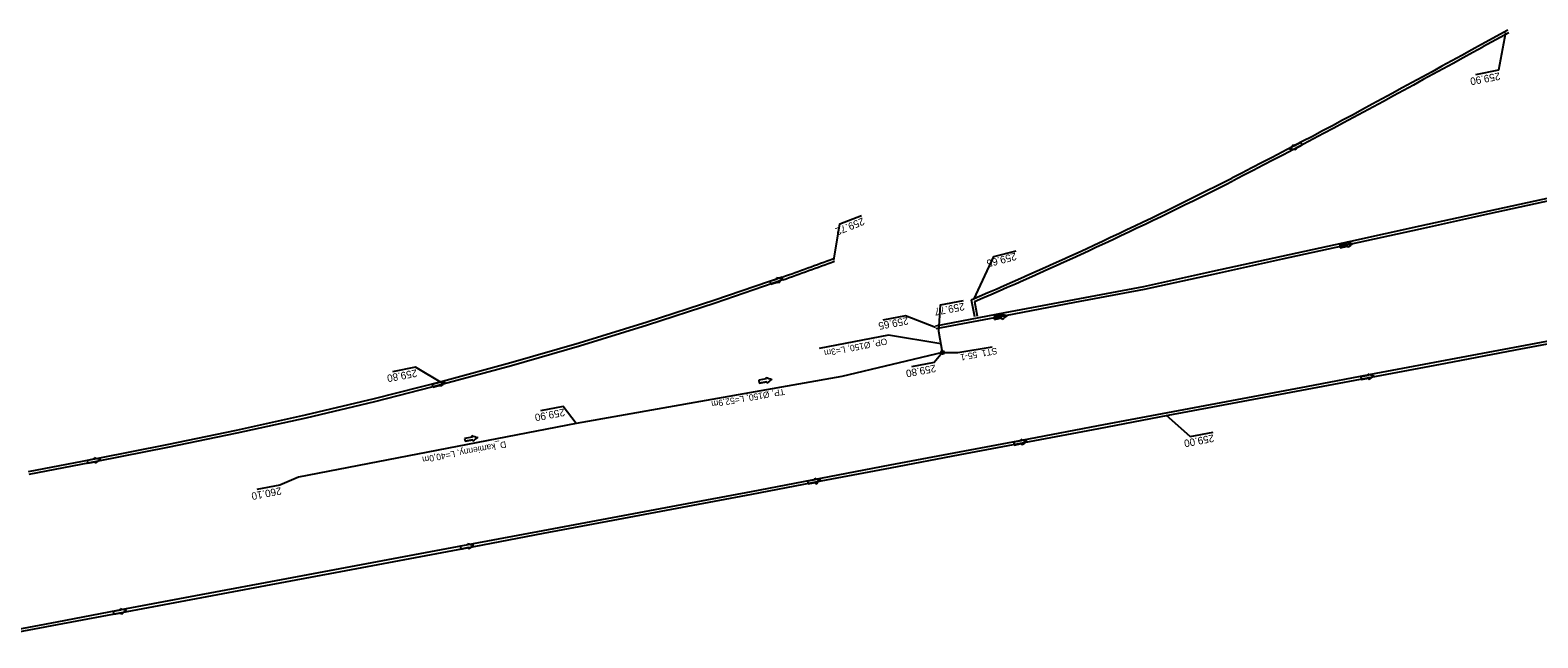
# Model space of a CAD drawing. Extents: x -1 to 65640748, y -22 to 5530284.
# Drawn here: x 6563824 to 6564037.5, y 5529873.9 to 5529959.9 of the extents above; entities that cross this region are included whole.
import ezdxf

# ---------------------------------------------------------------- set-up
doc = ezdxf.new("R2010")
doc.units = 0
for name, color, linetype in [('TOR_PS_ODW-drenaze', 7, 'Continuous'), ('TOR_PS_ODW-kolektory', 7, 'Continuous'), ('TOR_PS_ODW-studnie PEHD', 7, 'Continuous'), ('TOR_PS_OPIS_O-opisy rurociagow', 7, 'Continuous'), ('TOR_PS_OPIS_O-opisy studni', 7, 'Continuous'), ('TOR_PS_OPIS_T-INFO', 7, 'Continuous'), ('TOR_PS_T-rowy otwarte umocnione', 7, 'Continuous')]:
    doc.layers.add(name, color=color, linetype=linetype)

msp = doc.modelspace()

# ---------------------------------------------------------------- linework, layer by layer
at = {"layer": 'TOR_PS_ODW-drenaze'}
msp.add_line((6563901.29, 5529904.25), (6563862.01, 5529896.65), dxfattribs=at)
msp.add_lwpolyline([(6563953.18, 5529914.29), (6563938.93, 5529910.89), (6563901.29, 5529904.25)], dxfattribs=at)
at = {"layer": 'TOR_PS_ODW-kolektory'}
msp.add_line((6563953.18, 5529914.29), (6563952.63, 5529917.24), dxfattribs=at)
at = {"layer": 'TOR_PS_ODW-studnie PEHD'}
for radius in [0.25, 0.25, 0.25, 0.125, 0.125, 0.112]:
    msp.add_circle((6563953.18, 5529914.29), radius, dxfattribs=at)
at = {"layer": 'TOR_PS_OPIS_O-opisy rurociagow'}
for p, q in [((6564003.91, 5529944.02), (6564002.94, 5529943.51)), ((6564002.94, 5529943.51), (6564003.91, 5529944.02)), ((6564004.1, 5529943.67), (6564003.91, 5529944.02)), ((6564004.1, 5529943.67), (6564003.91, 5529944.02)), ((6564003.13, 5529943.16), (6564004.1, 5529943.67)), ((6564003.13, 5529943.16), (6564004.1, 5529943.67)), ((6564010.46, 5529929.73), (6564009.4, 5529929.5)), ((6564010.46, 5529929.73), (6564009.4, 5529929.5)), ((6564009.4, 5529929.5), (6564009.48, 5529929.11)), ((6564009.4, 5529929.5), (6564009.48, 5529929.11)), ((6564009.48, 5529929.11), (6564010.55, 5529929.34)), ((6564010.55, 5529929.34), (6564009.48, 5529929.11)), ((6563929.76, 5529924.68), (6563928.73, 5529924.33)), ((6563929.76, 5529924.68), (6563928.73, 5529924.33)), ((6563928.73, 5529924.33), (6563928.86, 5529923.95)), ((6563928.73, 5529924.33), (6563928.86, 5529923.95)), ((6563928.86, 5529923.95), (6563929.89, 5529924.3)), ((6563929.89, 5529924.3), (6563928.86, 5529923.95)), ((6563961.51, 5529919.57), (6563960.44, 5529919.37)), ((6563961.51, 5529919.57), (6563960.44, 5529919.37)), ((6563960.44, 5529919.37), (6563960.51, 5529918.98)), ((6563960.44, 5529919.37), (6563960.51, 5529918.98)), ((6563960.51, 5529918.98), (6563961.59, 5529919.18)), ((6563961.59, 5529919.18), (6563960.51, 5529918.98)), ((6563881.96, 5529910.07), (6563880.91, 5529909.78)), ((6563881.96, 5529910.07), (6563880.91, 5529909.78)), ((6563880.91, 5529909.78), (6563881.01, 5529909.39)), ((6563880.91, 5529909.78), (6563881.01, 5529909.39)), ((6563928.22, 5529910.55), (6563927.15, 5529910.36)), ((6563928.22, 5529910.55), (6563927.15, 5529910.36)), ((6563927.15, 5529910.36), (6563927.22, 5529909.97)), ((6563927.15, 5529910.36), (6563927.22, 5529909.97)), ((6563927.22, 5529909.97), (6563928.29, 5529910.16)), ((6563928.29, 5529910.16), (6563927.22, 5529909.97)), ((6564013.46, 5529911.06), (6564012.38, 5529910.86)), ((6564013.46, 5529911.06), (6564012.38, 5529910.86)), ((6564012.38, 5529910.86), (6564012.46, 5529910.46)), ((6564012.38, 5529910.86), (6564012.46, 5529910.46)), ((6564012.46, 5529910.46), (6564013.53, 5529910.67)), ((6564013.53, 5529910.67), (6564012.46, 5529910.46)), ((6563881.01, 5529909.39), (6563882.06, 5529909.68)), ((6563882.06, 5529909.68), (6563881.01, 5529909.39)), ((6563886.59, 5529902.34), (6563885.51, 5529902.15)), ((6563886.59, 5529902.34), (6563885.51, 5529902.15)), ((6563885.51, 5529902.15), (6563885.58, 5529901.76)), ((6563885.51, 5529902.15), (6563885.58, 5529901.76)), ((6563885.58, 5529901.76), (6563886.66, 5529901.95)), ((6563886.66, 5529901.95), (6563885.58, 5529901.76)), ((6563964.32, 5529901.8), (6563963.25, 5529901.6)), ((6563964.32, 5529901.8), (6563963.25, 5529901.6)), ((6563963.25, 5529901.6), (6563963.32, 5529901.2)), ((6563963.25, 5529901.6), (6563963.32, 5529901.2)), ((6563963.32, 5529901.2), (6563964.39, 5529901.41)), ((6563964.39, 5529901.41), (6563963.32, 5529901.2)), ((6563833.16, 5529899.23), (6563832.09, 5529899.02)), ((6563833.16, 5529899.23), (6563832.09, 5529899.02)), ((6563832.09, 5529899.02), (6563832.16, 5529898.63)), ((6563832.09, 5529899.02), (6563832.16, 5529898.63)), ((6563832.16, 5529898.63), (6563833.23, 5529898.84)), ((6563833.23, 5529898.84), (6563832.16, 5529898.63)), ((6563935.14, 5529896.29), (6563934.06, 5529896.09)), ((6563935.14, 5529896.29), (6563934.06, 5529896.09)), ((6563934.06, 5529896.09), (6563934.14, 5529895.7)), ((6563934.06, 5529896.09), (6563934.14, 5529895.7)), ((6563934.14, 5529895.7), (6563935.21, 5529895.9)), ((6563935.21, 5529895.9), (6563934.14, 5529895.7)), ((6563885.99, 5529887.08), (6563884.92, 5529886.88)), ((6563885.99, 5529887.08), (6563884.92, 5529886.88)), ((6563884.92, 5529886.88), (6563884.99, 5529886.49)), ((6563884.92, 5529886.88), (6563884.99, 5529886.49)), ((6563884.99, 5529886.49), (6563886.06, 5529886.69)), ((6563886.06, 5529886.69), (6563884.99, 5529886.49)), ((6563836.85, 5529877.87), (6563835.77, 5529877.67)), ((6563836.85, 5529877.87), (6563835.77, 5529877.67)), ((6563835.77, 5529877.67), (6563835.85, 5529877.28)), ((6563835.77, 5529877.67), (6563835.85, 5529877.28)), ((6563835.85, 5529877.28), (6563836.92, 5529877.48)), ((6563836.92, 5529877.48), (6563835.85, 5529877.28))]:
    msp.add_line(p, q, dxfattribs=at)
for points in [[(6564002.85, 5529943.72), (6564002.85, 5529943.72)], [(6564003.25, 5529942.96), (6564003.25, 5529942.96)], [(6564010.41, 5529929.95), (6564010.41, 5529929.95)], [(6564010.59, 5529929.12), (6564010.59, 5529929.12)], [(6563929.68, 5529924.89), (6563929.68, 5529924.89)], [(6563929.95, 5529924.09), (6563929.95, 5529924.09)], [(6563961.46, 5529919.79), (6563961.46, 5529919.79)], [(6563961.62, 5529918.96), (6563961.62, 5529918.96)], [(6563881.89, 5529910.28), (6563881.89, 5529910.28)], [(6563928.18, 5529910.77), (6563928.18, 5529910.77)], [(6563928.32, 5529909.94), (6563928.32, 5529909.94)], [(6564013.4, 5529911.28), (6564013.4, 5529911.28)], [(6564013.56, 5529910.44), (6564013.56, 5529910.44)], [(6563882.11, 5529909.46), (6563882.11, 5529909.46)], [(6563886.54, 5529902.56), (6563886.54, 5529902.56)], [(6563886.69, 5529901.73), (6563886.69, 5529901.73)], [(6563964.27, 5529902.02), (6563964.27, 5529902.02)], [(6563964.43, 5529901.18), (6563964.43, 5529901.18)], [(6563833.1, 5529899.45), (6563833.1, 5529899.45)], [(6563833.27, 5529898.62), (6563833.27, 5529898.62)], [(6563935.08, 5529896.51), (6563935.08, 5529896.51)], [(6563935.24, 5529895.67), (6563935.24, 5529895.67)], [(6563885.94, 5529887.3), (6563885.94, 5529887.3)], [(6563886.1, 5529886.47), (6563886.1, 5529886.47)], [(6563836.79, 5529878.09), (6563836.79, 5529878.09)], [(6563836.95, 5529877.26), (6563836.95, 5529877.26)]]:
    msp.add_lwpolyline(points, dxfattribs=at)
for centre, radius, start, end in [((6563998.52, 5529946.05), 4.92, 321.277, 331.6588), ((6563998.52, 5529946.05), 4.92, 321.277, 331.6588), ((6564002.75, 5529938.07), 4.92, 84.2391, 94.6209), ((6564002.75, 5529938.07), 4.92, 84.2391, 94.6209), ((6564002.5, 5529943.42), 0.458, 11.083, 39.5442), ((6564002.5, 5529943.42), 0.458, 11.083, 39.5442), ((6564002.81, 5529942.84), 0.458, 16.3536, 44.8149), ((6564002.81, 5529942.84), 0.458, 16.3536, 44.8149), ((6564012.19, 5529934.53), 4.92, 248.6761, 259.0579), ((6564010.86, 5529929.96), 0.458, 180.7907, 209.2519), ((6564012.19, 5529934.53), 4.92, 248.6761, 259.0579), ((6564010.86, 5529929.96), 0.458, 180.7907, 209.2519), ((6564011.01, 5529929.31), 0.458, 175.52, 203.9812), ((6564011.01, 5529929.31), 0.458, 175.52, 203.9812), ((6564014.13, 5529925.71), 4.92, 125.714, 136.0958), ((6564014.13, 5529925.71), 4.92, 125.714, 136.0958), ((6563930.93, 5529929.65), 4.92, 255.2121, 265.5939), ((6563930.13, 5529924.95), 0.458, 187.3266, 215.7879), ((6563930.93, 5529929.65), 4.92, 255.2121, 265.5939), ((6563930.13, 5529924.95), 0.458, 187.3266, 215.7879), ((6563933.86, 5529921.1), 4.92, 132.25, 142.6318), ((6563933.86, 5529921.1), 4.92, 132.25, 142.6318), ((6563930.35, 5529924.32), 0.458, 182.056, 210.5172), ((6563930.35, 5529924.32), 0.458, 182.056, 210.5172), ((6563963.38, 5529924.32), 4.92, 247.0619, 257.4437), ((6563961.92, 5529919.79), 0.458, 179.1764, 207.6377), ((6563963.38, 5529924.32), 4.92, 247.0619, 257.4437), ((6563961.92, 5529919.79), 0.458, 179.1764, 207.6377), ((6563962.04, 5529919.13), 0.458, 173.9058, 202.367), ((6563962.04, 5529919.13), 0.458, 173.9058, 202.367), ((6563965.07, 5529915.45), 4.92, 124.0997, 134.4816), ((6563965.07, 5529915.45), 4.92, 124.0997, 134.4816), ((6563883.45, 5529914.94), 4.92, 251.4629, 261.8448), ((6563882.35, 5529910.31), 0.458, 183.5775, 212.0387), ((6563883.45, 5529914.94), 4.92, 251.4629, 261.8448), ((6563882.35, 5529910.31), 0.458, 183.5775, 212.0387), ((6563885.82, 5529906.23), 4.92, 128.5008, 138.8826), ((6563885.82, 5529906.23), 4.92, 128.5008, 138.8826), ((6563930.15, 5529915.28), 4.92, 246.381, 256.7628), ((6563928.63, 5529910.76), 0.458, 178.4955, 206.9568), ((6563930.15, 5529915.28), 4.92, 246.381, 256.7628), ((6563928.63, 5529910.76), 0.458, 178.4955, 206.9568), ((6563928.75, 5529910.11), 0.458, 173.2249, 201.6861), ((6563928.75, 5529910.11), 0.458, 173.2249, 201.6861), ((6563931.73, 5529906.39), 4.92, 123.4189, 133.8007), ((6563931.73, 5529906.39), 4.92, 123.4189, 133.8007), ((6564015.33, 5529915.8), 4.92, 246.9517, 257.3335), ((6564013.86, 5529911.27), 0.458, 179.0663, 207.5275), ((6564015.33, 5529915.8), 4.92, 246.9517, 257.3335), ((6564013.86, 5529911.27), 0.458, 179.0663, 207.5275), ((6564013.98, 5529910.62), 0.458, 173.7956, 202.2568), ((6564013.98, 5529910.62), 0.458, 173.7956, 202.2568), ((6564017, 5529906.93), 4.92, 123.9896, 134.3714), ((6564017, 5529906.93), 4.92, 123.9896, 134.3714), ((6563882.52, 5529909.67), 0.458, 178.3068, 206.7681), ((6563882.52, 5529909.67), 0.458, 178.3068, 206.7681), ((6563888.51, 5529907.07), 4.92, 246.381, 256.7628), ((6563887, 5529902.55), 0.458, 178.4955, 206.9568), ((6563888.51, 5529907.07), 4.92, 246.381, 256.7628), ((6563887, 5529902.55), 0.458, 178.4955, 206.9568), ((6563887.11, 5529901.9), 0.458, 173.2249, 201.6861), ((6563887.11, 5529901.9), 0.458, 173.2249, 201.6861), ((6563890.09, 5529898.18), 4.92, 123.4189, 133.8007), ((6563890.09, 5529898.18), 4.92, 123.4189, 133.8007), ((6563966.19, 5529906.54), 4.92, 246.9742, 257.356), ((6563964.73, 5529902.01), 0.458, 179.0888, 207.55), ((6563966.19, 5529906.54), 4.92, 246.9742, 257.356), ((6563964.73, 5529902.01), 0.458, 179.0888, 207.55), ((6563964.85, 5529901.36), 0.458, 173.8181, 202.2794), ((6563964.85, 5529901.36), 0.458, 173.8181, 202.2794), ((6563967.87, 5529897.67), 4.92, 124.0121, 134.3939), ((6563967.87, 5529897.67), 4.92, 124.0121, 134.3939), ((6563834.99, 5529903.99), 4.92, 247.4115, 257.7933), ((6563833.56, 5529899.45), 0.458, 179.526, 207.9873), ((6563834.99, 5529903.99), 4.92, 247.4115, 257.7933), ((6563833.56, 5529899.45), 0.458, 179.526, 207.9873), ((6563836.73, 5529895.13), 4.92, 124.4493, 134.8312), ((6563836.73, 5529895.13), 4.92, 124.4493, 134.8312), ((6563833.69, 5529898.79), 0.458, 174.2554, 202.7166), ((6563833.69, 5529898.79), 0.458, 174.2554, 202.7166), ((6563937.01, 5529901.03), 4.92, 246.9024, 257.2843), ((6563935.54, 5529896.5), 0.458, 179.017, 207.4782), ((6563937.01, 5529901.03), 4.92, 246.9024, 257.2843), ((6563935.54, 5529896.5), 0.458, 179.017, 207.4782), ((6563935.66, 5529895.85), 0.458, 173.7463, 202.2076), ((6563935.66, 5529895.85), 0.458, 173.7463, 202.2076), ((6563938.68, 5529892.16), 4.92, 123.9403, 134.3221), ((6563938.68, 5529892.16), 4.92, 123.9403, 134.3221), ((6563887.87, 5529891.82), 4.92, 246.9024, 257.2843), ((6563886.4, 5529887.29), 0.458, 179.017, 207.4782), ((6563887.87, 5529891.82), 4.92, 246.9024, 257.2843), ((6563886.4, 5529887.29), 0.458, 179.017, 207.4782), ((6563886.52, 5529886.64), 0.458, 173.7463, 202.2076), ((6563886.52, 5529886.64), 0.458, 173.7463, 202.2076), ((6563889.53, 5529882.95), 4.92, 123.9403, 134.3221), ((6563889.53, 5529882.95), 4.92, 123.9403, 134.3221), ((6563838.72, 5529882.62), 4.92, 246.9024, 257.2843), ((6563837.25, 5529878.08), 0.458, 179.017, 207.4782), ((6563838.72, 5529882.62), 4.92, 246.9024, 257.2843), ((6563837.25, 5529878.08), 0.458, 179.017, 207.4782), ((6563840.39, 5529873.74), 4.92, 123.9403, 134.3221), ((6563840.39, 5529873.74), 4.92, 123.9403, 134.3221), ((6563837.37, 5529877.43), 0.458, 173.7463, 202.2076), ((6563837.37, 5529877.43), 0.458, 173.7463, 202.2076)]:
    msp.add_arc(centre, radius, start, end, dxfattribs=at)
at = {"layer": 'TOR_PS_OPIS_T-INFO'}
for points in [[(6564032.88, 5529959.52), (6564031.88, 5529954.21), (6564028.65, 5529953.58)], [(6563937.81, 5529927.36), (6563938.63, 5529932.48), (6563941.68, 5529933.69)], [(6563957.6, 5529921.79), (6563960.42, 5529927.86), (6563963.61, 5529928.69)], [(6563952.63, 5529917.24), (6563952.9, 5529921.03), (6563956.14, 5529921.63)], [(6563952.2, 5529917.82), (6563947.94, 5529919.5), (6563944.71, 5529918.87)], [(6563952.92, 5529915.53), (6563945.52, 5529916.73), (6563935.7, 5529914.84)], [(6563953.18, 5529914.29), (6563952.01, 5529912.89), (6563948.78, 5529912.26)], [(6563953.18, 5529914.29), (6563955.35, 5529914.28), (6563960.19, 5529915.08)], [(6563882.43, 5529909.92), (6563878.55, 5529912.21), (6563875.31, 5529911.58)], [(6563901.29, 5529904.25), (6563899.47, 5529906.67), (6563896.24, 5529906.05)], [(6563984.77, 5529905.49), (6563988.23, 5529902.41), (6563991.47, 5529903.01)], [(6563862.01, 5529896.65), (6563859.35, 5529895.54), (6563856.12, 5529894.92)]]:
    msp.add_lwpolyline(points, dxfattribs=at)
at = {"layer": 'TOR_PS_T-rowy otwarte umocnione'}
for p, q in [((6564033.19, 5529959.88), (6564029.49, 5529957.85)), ((6564033.37, 5529959.52), (6564029.68, 5529957.5)), ((6563957.25, 5529921.75), (6563957.71, 5529919.37)), ((6563957.71, 5529921.51), (6563958.1, 5529919.45))]:
    msp.add_line(p, q, dxfattribs=at)
for points in [[(6564029.49, 5529957.85), (6564028.09, 5529957.08), (6564026.68, 5529956.31), (6564025.28, 5529955.54), (6564023.87, 5529954.77), (6564022.47, 5529954), (6564021.06, 5529953.23), (6564019.66, 5529952.47), (6564018.25, 5529951.7), (6564016.84, 5529950.93), (6564015.43, 5529950.17), (6564014.02, 5529949.41), (6564012.61, 5529948.64), (6564011.2, 5529947.88), (6564009.78, 5529947.13), (6564008.37, 5529946.37), (6564006.95, 5529945.62), (6564005.53, 5529944.86), (6564004.11, 5529944.11), (6564002.69, 5529943.37), (6564001.26, 5529942.62), (6563999.84, 5529941.88), (6563998.41, 5529941.14), (6563996.98, 5529940.4), (6563995.55, 5529939.67), (6563994.12, 5529938.94)], [(6564029.67, 5529957.49), (6564028.27, 5529956.72), (6564026.86, 5529955.95), (6564025.46, 5529955.18), (6564024.06, 5529954.41), (6564022.65, 5529953.65), (6564021.24, 5529952.88), (6564019.84, 5529952.11), (6564018.43, 5529951.34), (6564017.02, 5529950.58), (6564015.61, 5529949.81), (6564014.2, 5529949.05), (6564012.79, 5529948.29), (6564011.38, 5529947.53), (6564009.96, 5529946.77), (6564008.55, 5529946.01), (6564007.13, 5529945.26), (6564005.71, 5529944.51), (6564004.29, 5529943.76), (6564002.87, 5529943.01), (6564001.44, 5529942.26), (6564000.02, 5529941.52), (6563998.59, 5529940.78), (6563997.16, 5529940.05), (6563995.73, 5529939.31), (6563994.3, 5529938.59)], [(6564040.27, 5529936.42), (6564030.5, 5529934.28), (6564020.73, 5529932.15), (6564010.95, 5529930.01), (6564001.18, 5529927.87), (6563991.41, 5529925.74), (6563981.64, 5529923.6), (6563971.81, 5529921.74), (6563961.98, 5529919.88), (6563952.16, 5529918.02)], [(6564040.35, 5529936.03), (6564030.58, 5529933.89), (6564020.8, 5529931.75), (6564011.03, 5529929.62), (6564001.26, 5529927.48), (6563991.48, 5529925.34), (6563981.71, 5529923.21), (6563971.88, 5529921.35), (6563962.06, 5529919.49), (6563952.23, 5529917.63)], [(6563930.49, 5529924.96), (6563920.93, 5529921.68), (6563911.34, 5529918.56), (6563901.73, 5529915.6), (6563892.08, 5529912.81), (6563882.4, 5529910.18), (6563872.69, 5529907.72), (6563862.95, 5529905.41), (6563853.18, 5529903.26), (6563843.38, 5529901.24), (6563833.57, 5529899.31), (6563823.75, 5529897.43)], [(6563930.56, 5529924.56), (6563921.01, 5529921.28), (6563911.42, 5529918.17), (6563901.8, 5529915.21), (6563892.15, 5529912.42), (6563882.47, 5529909.79), (6563872.76, 5529907.32), (6563863.02, 5529905.02), (6563853.25, 5529902.87), (6563843.46, 5529900.85), (6563833.64, 5529898.92), (6563823.82, 5529897.04)], [(6564043.98, 5529916.84), (6564034.16, 5529914.99), (6564024.33, 5529913.15), (6564014.5, 5529911.3), (6564004.67, 5529909.45), (6563994.85, 5529907.6), (6563985.02, 5529905.75), (6563975.19, 5529903.9), (6563965.36, 5529902.05), (6563955.54, 5529900.2), (6563945.71, 5529898.35), (6563935.88, 5529896.49)], [(6564044.06, 5529916.45), (6564034.23, 5529914.6), (6564024.4, 5529912.75), (6564014.58, 5529910.91), (6564004.75, 5529909.06), (6563994.92, 5529907.21), (6563985.09, 5529905.36), (6563975.27, 5529903.51), (6563965.44, 5529901.66), (6563955.61, 5529899.81), (6563945.78, 5529897.95), (6563935.96, 5529896.1)], [(6563935.88, 5529896.49), (6563926.07, 5529894.59), (6563916.24, 5529892.75), (6563906.41, 5529890.91), (6563896.58, 5529889.07), (6563886.75, 5529887.22), (6563876.92, 5529885.38), (6563867.09, 5529883.54), (6563857.26, 5529881.7), (6563847.43, 5529879.86), (6563837.6, 5529878.02), (6563827.78, 5529876.17), (6563817.95, 5529874.33)], [(6563935.96, 5529896.1), (6563926.14, 5529894.2), (6563916.31, 5529892.36), (6563906.48, 5529890.51), (6563896.65, 5529888.67), (6563886.82, 5529886.83), (6563877, 5529884.99), (6563867.17, 5529883.15), (6563857.34, 5529881.31), (6563847.51, 5529879.46), (6563837.68, 5529877.62), (6563827.85, 5529875.78), (6563818.02, 5529873.94)]]:
    msp.add_lwpolyline(points, dxfattribs=at)
for centre, radius, start, end in [((6563713.11, 5530493.29), 621.5, 293.13043, 296.88094), ((6563713.11, 5530493.29), 621.9, 293.16006, 296.88094), ((6563727.04, 5530500.93), 610.85, 289.45397, 290.17631), ((6563727.12, 5530500.54), 610.85, 289.45397, 290.18284)]:
    msp.add_arc(centre, radius, start, end, dxfattribs=at)

# ---------------------------------------------------------------- texts
at = {"layer": 'TOR_PS_OPIS_O-opisy rurociagow'}
for s, rotation, p in [('OP, Ø150, L=3m', 190.9287, (6563945.25, 5529916.32)), ('TP, Ø150, L=52,9m', 189.9948, (6563930.76, 5529909.21)), ('D_kamienny, L=40,0m', 190.5985, (6563891.32, 5529901.75))]:
    msp.add_text(s, height=0.9, rotation=rotation, dxfattribs=at).set_placement(p)
at = {"layer": 'TOR_PS_OPIS_O-opisy studni'}
msp.add_text('ST1_55-1', height=0.9, rotation=190.5069, dxfattribs=at).set_placement((6563960.83, 5529914.98))
at = {"layer": 'TOR_PS_OPIS_T-INFO'}
for s, rotation, p in [('259.90', 190.7159, (6564032.02, 5529953.91)), ('259.72', 201.9022, (6563941.86, 5529933.4)), ('259.65', 194.74, (6563963.48, 5529928.43)), ('259.77', 190.7506, (6563956.18, 5529921.33)), ('259.65', 190.7159, (6563948.24, 5529919.32)), ('259.80', 190.7159, (6563878.68, 5529911.91)), ('259.80', 190.7159, (6563952.14, 5529912.59)), ('259.90', 190.7159, (6563899.6, 5529906.37)), ('259.00', 190.7506, (6563991.51, 5529902.71)), ('260.10', 190.7159, (6563859.48, 5529895.25))]:
    msp.add_text(s, height=1.05, rotation=rotation, dxfattribs=at).set_placement(p)

doc.saveas('drawing.dxf')
